Omron CX-Programmer project 新規ﾌﾟﾛｼﾞｪｸﾄ (CX-Programmer 9.61)

# PLC NewPLC1: CJ2M CPU12
I/O table (CPU CJ2M-CPU12): rack 0 slot 0 CJ1W-SCU42

## Global symbols (name address type ; comment)
5551 CHANNEL  ; RecieveData[50]

## Program NewProgram1 (cyclic task 0)
Local symbols
CommPortEnabledFlag_P7 A202.07 BOOL
Input_Start 5000.00 BOOL
Local_ControlWord1 5010 UINT
Local_ControlWord2 5011 UINT
Local_DestinationDeviceError 5000.06 BOOL
Local_FirstReceiveWord 5500 UINT
Local_FirstSendWord 5020 UINT
Local_PMCRErrorCode 5000.07 BOOL
Local_PMCRErrorEnd 5000.05 BOOL
Local_PMCRExecuting 5000.01 BOOL
Local_PMCRNormalEnd 5000.04 BOOL
Local_PMCR_ErrorCode 5012 UINT
Output_DestinationDeviceErrorCode H402 UINT
Output_ErrorEnd 5000.03 BOOL
Output_NormalEnd 5000.02 BOOL
Output_PMCR_ErrorCode H400 UINT
ProtocolMacroErrorCode_SCU_0_P2 1519 UINT
ProtocolMacroExecuting_SCU_0_P2 1519.15 BOOL
ReceiveData 5501 WORD[50]
SequenceAbortEndCompletion_SCU_0_P2 1519.10 BOOL
SequenceEndCompletion_SCU_0_P2 1519.11 BOOL
TransmissionError_SCU_0_P2 1518.15 BOOL

### Section Section1

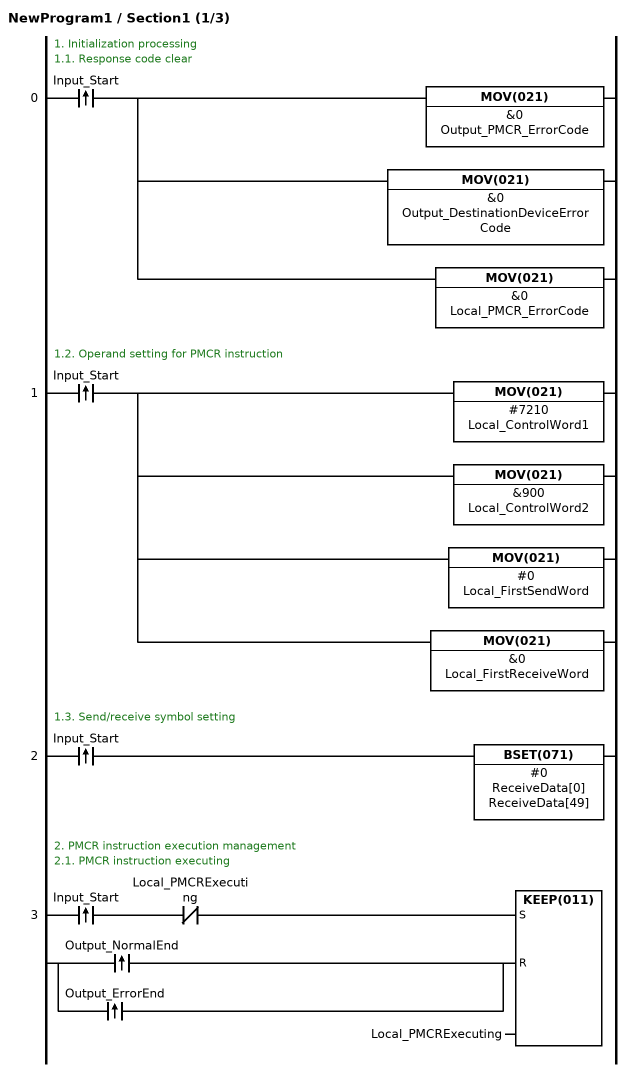
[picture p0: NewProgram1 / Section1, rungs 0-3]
; rung 0: 1. Initialization processing / 1.1. Response code clear
@LD Input_Start
MOV(021) &0 Output_PMCR_ErrorCode
MOV(021) &0 Output_DestinationDeviceErrorCode
MOV(021) &0 Local_PMCR_ErrorCode
; rung 1: 1.2. Operand setting for PMCR instruction
@LD Input_Start
MOV(021) #7210 Local_ControlWord1
MOV(021) &900 Local_ControlWord2
MOV(021) #0 Local_FirstSendWord
MOV(021) &0 Local_FirstReceiveWord
; rung 2: 1.3. Send/receive symbol setting
@LD Input_Start
BSET(071) #0 ReceiveData[0] ReceiveData[49]
; rung 3: 2. PMCR instruction execution management / 2.1. PMCR instruction executing
@LD Input_Start
ANDNOT Local_PMCRExecuting
@LD Output_NormalEnd
@OR Output_ErrorEnd
KEEP(011) Local_PMCRExecuting

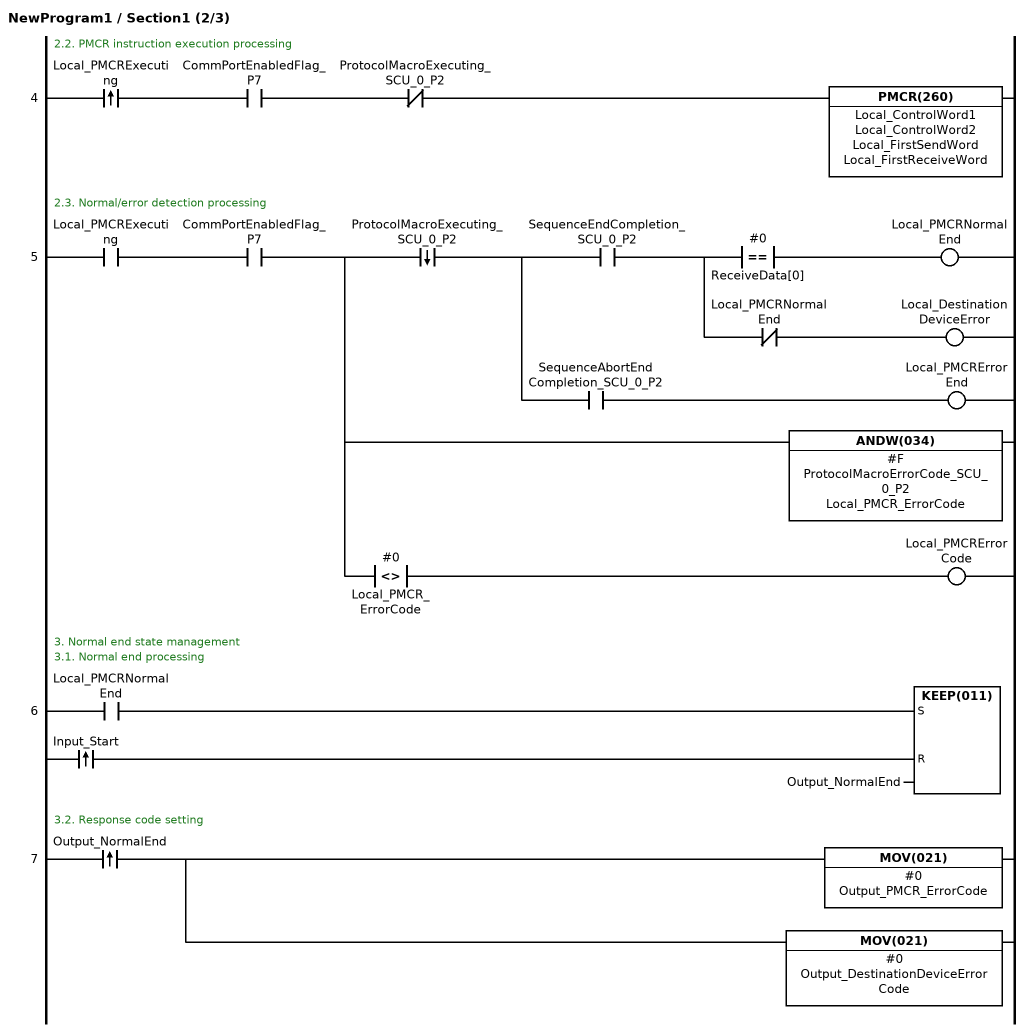
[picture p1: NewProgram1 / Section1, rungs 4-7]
; rung 4: 2.2. PMCR instruction execution processing
@LD Local_PMCRExecuting
AND CommPortEnabledFlag_P7
ANDNOT ProtocolMacroExecuting_SCU_0_P2
PMCR(260) Local_ControlWord1 Local_ControlWord2 Local_FirstSendWord Local_FirstReceiveWord
; rung 5: 2.3. Normal/error detection processing
LD Local_PMCRExecuting
AND CommPortEnabledFlag_P7
OUT TR0
%AND ProtocolMacroExecuting_SCU_0_P2
OUT TR1
AND SequenceEndCompletion_SCU_0_P2
OUT TR2
AND=(300) #0 ReceiveData[0]
OUT Local_PMCRNormalEnd
LD TR2
ANDNOT Local_PMCRNormalEnd
OUT Local_DestinationDeviceError
LD TR1
AND SequenceAbortEndCompletion_SCU_0_P2
OUT Local_PMCRErrorEnd
LD TR0
ANDW(034) #F ProtocolMacroErrorCode_SCU_0_P2 Local_PMCR_ErrorCode
AND<>(305) #0 Local_PMCR_ErrorCode
OUT Local_PMCRErrorCode
; rung 6: 3. Normal end state management / 3.1. Normal end processing
LD Local_PMCRNormalEnd
@LD Input_Start
KEEP(011) Output_NormalEnd
; rung 7: 3.2. Response code setting
@LD Output_NormalEnd
MOV(021) #0 Output_PMCR_ErrorCode
MOV(021) #0 Output_DestinationDeviceErrorCode

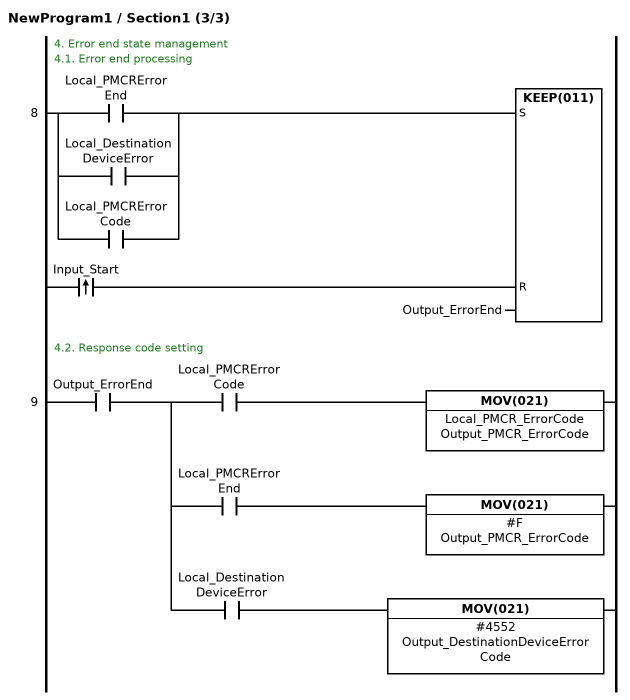
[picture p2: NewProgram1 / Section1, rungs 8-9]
; rung 8: 4. Error end state management / 4.1. Error end processing
LD Local_PMCRErrorEnd
OR Local_DestinationDeviceError
OR Local_PMCRErrorCode
@LD Input_Start
KEEP(011) Output_ErrorEnd
; rung 9: 4.2. Response code setting
LD Output_ErrorEnd
OUT TR0
AND Local_PMCRErrorCode
MOV(021) Local_PMCR_ErrorCode Output_PMCR_ErrorCode
LD TR0
AND Local_PMCRErrorEnd
MOV(021) #F Output_PMCR_ErrorCode
LD TR0
AND Local_DestinationDeviceError
MOV(021) #4552 Output_DestinationDeviceErrorCode

### Section END
; rung 0
END(001)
